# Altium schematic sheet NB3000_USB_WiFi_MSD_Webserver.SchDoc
size B; DocumentNumber: 1; SheetNumber: 1; SheetTotal: 1
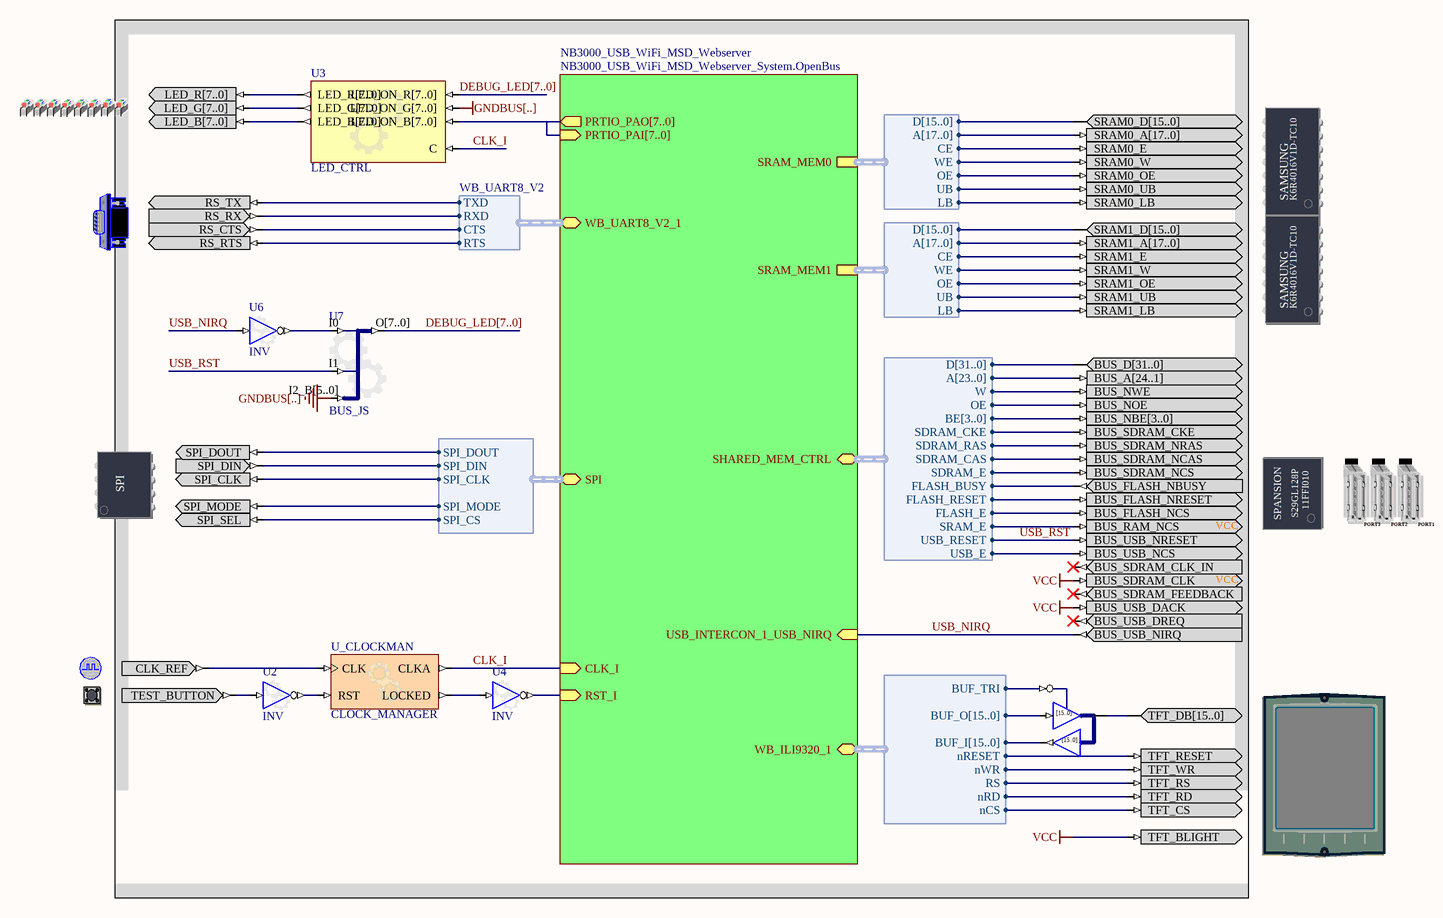
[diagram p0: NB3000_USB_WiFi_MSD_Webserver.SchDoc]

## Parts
(Parts that share a designator on the sheet are numbered #1, #2 ... from top to bottom, then left to right.)
?#1  LEDS_RGB  (value not drawn)
?#2  SRAM_DAUGHTER0  (value not drawn)
?#3  RS232CNTR  (value not drawn)
?#4  SRAM_DAUGHTER1  (value not drawn)
?#5  SHARED_FLASH_USB  (value not drawn)
?#6  SERIALFMEMORY  (value not drawn)
?#7  CLOCK_REFERENCE  (value not drawn)
?#8  TEST_BUTTON  (value not drawn)
?#9  TFT_LCD  (value not drawn)
U1  IOBUF16B  (value not drawn)
U2  INV
U3  LED_CTRL
U4  INV
U6  INV
U7  BUS_JS
U_CLOCKMAN  CLOCK_MANAGER

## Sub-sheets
NB3000_USB_WiFi_MSD_Webserver = NB3000_USB_WiFi_MSD_Webserver_System.OpenBus: SRAM_MEM0 (harness WB_MEM_CTRL_SRAM16_A18), SRAM_MEM1 (harness WB_MEM_CTRL_SRAM16_A18), RST_I (in), CLK_I (in), SHARED_MEM_CTRL (harness WB_SHARED_MEM_CTRL), USB_INTERCON_1_USB_NIRQ (in), PRTIO_PAO[7..0] (out), PRTIO_PAI[7..0] (in), WB_UART8_V2_1 (harness WB_UART8_V2), SPI (harness SPI_W_NB), WB_ILI9320_1 (harness VGA32_ILI9320)

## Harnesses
WB_MEM_CTRL_SRAM16_A18: D[15..0], A[17..0], CE, WE, OE, UB, LB
WB_SHARED_MEM_CTRL: D[31..0], A[23..0], W, OE, BE[3..0], SDRAM_CKE, SDRAM_RAS, SDRAM_CAS, SDRAM_E, FLASH_BUSY, FLASH_RESET, FLASH_E, SRAM_E, USB_RESET, USB_E
WB_UART8_V2: TXD, RXD, CTS, RTS
SPI_W_NB: SPI_DOUT, SPI_DIN, SPI_CLK, SPI_MODE, SPI_CS
VGA32_ILI9320: BUF_TRI, BUF_O[15..0], BUF_I[15..0], nRESET, nWR, RS, nRD, nCS

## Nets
GNDBUS[..]: U3.LED_ON_G[7..0] U7.I2_B[5..0]
VCC: ?#5.BUS_SDRAM_CLK ?#5.BUS_USB_DACK ?#9.TFT_BLIGHT
CLK_I: U3.C U_CLOCKMAN.CLKA ; sheet NB3000_USB_WiFi_MSD_Webserver/CLK_I
USB_NIRQ: ?#5.BUS_USB_NIRQ U6.I ; sheet NB3000_USB_WiFi_MSD_Webserver/USB_INTERCON_1_USB_NIRQ
USB_RST: ?#5.BUS_USB_NRESET U7.I1 ; sheet NB3000_USB_WiFi_MSD_Webserver/SHARED_MEM_CTRL.USB_RESET
Net?#2_SRAM0_E: ?#2.SRAM0_E ; sheet NB3000_USB_WiFi_MSD_Webserver/SRAM_MEM0.CE
Net?#2_SRAM0_LB: ?#2.SRAM0_LB ; sheet NB3000_USB_WiFi_MSD_Webserver/SRAM_MEM0.LB
Net?#2_SRAM0_OE: ?#2.SRAM0_OE ; sheet NB3000_USB_WiFi_MSD_Webserver/SRAM_MEM0.OE
Net?#2_SRAM0_UB: ?#2.SRAM0_UB ; sheet NB3000_USB_WiFi_MSD_Webserver/SRAM_MEM0.UB
Net?#2_SRAM0_W: ?#2.SRAM0_W ; sheet NB3000_USB_WiFi_MSD_Webserver/SRAM_MEM0.WE
Net?#3_RS_CTS: ?#3.RS_CTS ; sheet NB3000_USB_WiFi_MSD_Webserver/WB_UART8_V2_1.CTS
Net?#3_RS_RTS: ?#3.RS_RTS ; sheet NB3000_USB_WiFi_MSD_Webserver/WB_UART8_V2_1.RTS
Net?#3_RS_RX: ?#3.RS_RX ; sheet NB3000_USB_WiFi_MSD_Webserver/WB_UART8_V2_1.RXD
Net?#3_RS_TX: ?#3.RS_TX ; sheet NB3000_USB_WiFi_MSD_Webserver/WB_UART8_V2_1.TXD
Net?#4_SRAM1_E: ?#4.SRAM1_E ; sheet NB3000_USB_WiFi_MSD_Webserver/SRAM_MEM1.CE
Net?#4_SRAM1_LB: ?#4.SRAM1_LB ; sheet NB3000_USB_WiFi_MSD_Webserver/SRAM_MEM1.LB
Net?#4_SRAM1_OE: ?#4.SRAM1_OE ; sheet NB3000_USB_WiFi_MSD_Webserver/SRAM_MEM1.OE
Net?#4_SRAM1_UB: ?#4.SRAM1_UB ; sheet NB3000_USB_WiFi_MSD_Webserver/SRAM_MEM1.UB
Net?#4_SRAM1_W: ?#4.SRAM1_W ; sheet NB3000_USB_WiFi_MSD_Webserver/SRAM_MEM1.WE
Net?#5_BUS_FLASH_NBUSY: ?#5.BUS_FLASH_NBUSY ; sheet NB3000_USB_WiFi_MSD_Webserver/SHARED_MEM_CTRL.FLASH_BUSY
Net?#5_BUS_FLASH_NCS: ?#5.BUS_FLASH_NCS ; sheet NB3000_USB_WiFi_MSD_Webserver/SHARED_MEM_CTRL.FLASH_E
Net?#5_BUS_FLASH_NRESET: ?#5.BUS_FLASH_NRESET ; sheet NB3000_USB_WiFi_MSD_Webserver/SHARED_MEM_CTRL.FLASH_RESET
Net?#5_BUS_NOE: ?#5.BUS_NOE ; sheet NB3000_USB_WiFi_MSD_Webserver/SHARED_MEM_CTRL.OE
Net?#5_BUS_NWE: ?#5.BUS_NWE ; sheet NB3000_USB_WiFi_MSD_Webserver/SHARED_MEM_CTRL.W
Net?#5_BUS_RAM_NCS: ?#5.BUS_RAM_NCS ; sheet NB3000_USB_WiFi_MSD_Webserver/SHARED_MEM_CTRL.SRAM_E
Net?#5_BUS_SDRAM_CKE: ?#5.BUS_SDRAM_CKE ; sheet NB3000_USB_WiFi_MSD_Webserver/SHARED_MEM_CTRL.SDRAM_CKE
Net?#5_BUS_SDRAM_NCAS: ?#5.BUS_SDRAM_NCAS ; sheet NB3000_USB_WiFi_MSD_Webserver/SHARED_MEM_CTRL.SDRAM_CAS
Net?#5_BUS_SDRAM_NCS: ?#5.BUS_SDRAM_NCS ; sheet NB3000_USB_WiFi_MSD_Webserver/SHARED_MEM_CTRL.SDRAM_E
Net?#5_BUS_SDRAM_NRAS: ?#5.BUS_SDRAM_NRAS ; sheet NB3000_USB_WiFi_MSD_Webserver/SHARED_MEM_CTRL.SDRAM_RAS
Net?#5_BUS_USB_NCS: ?#5.BUS_USB_NCS ; sheet NB3000_USB_WiFi_MSD_Webserver/SHARED_MEM_CTRL.USB_E
Net?#6_SPI_CLK: ?#6.SPI_CLK ; sheet NB3000_USB_WiFi_MSD_Webserver/SPI.SPI_CLK
Net?#6_SPI_DIN: ?#6.SPI_DIN ; sheet NB3000_USB_WiFi_MSD_Webserver/SPI.SPI_DIN
Net?#6_SPI_DOUT: ?#6.SPI_DOUT ; sheet NB3000_USB_WiFi_MSD_Webserver/SPI.SPI_DOUT
Net?#6_SPI_MODE: ?#6.SPI_MODE ; sheet NB3000_USB_WiFi_MSD_Webserver/SPI.SPI_MODE
Net?#6_SPI_SEL: ?#6.SPI_SEL ; sheet NB3000_USB_WiFi_MSD_Webserver/SPI.SPI_CS
Net?#7_CLK_REF: ?#7.CLK_REF U_CLOCKMAN.CLK
Net?#8_TEST_BUTTON: ?#8.TEST_BUTTON U2.I
Net?#9_TFT_CS: ?#9.TFT_CS ; sheet NB3000_USB_WiFi_MSD_Webserver/WB_ILI9320_1.nCS
Net?#9_TFT_RD: ?#9.TFT_RD ; sheet NB3000_USB_WiFi_MSD_Webserver/WB_ILI9320_1.nRD
Net?#9_TFT_RESET: ?#9.TFT_RESET ; sheet NB3000_USB_WiFi_MSD_Webserver/WB_ILI9320_1.nRESET
Net?#9_TFT_RS: ?#9.TFT_RS ; sheet NB3000_USB_WiFi_MSD_Webserver/WB_ILI9320_1.RS
Net?#9_TFT_WR: ?#9.TFT_WR ; sheet NB3000_USB_WiFi_MSD_Webserver/WB_ILI9320_1.nWR
NetU1_T: U1.T ; sheet NB3000_USB_WiFi_MSD_Webserver/WB_ILI9320_1.BUF_TRI
NetU2_O: U2.O U_CLOCKMAN.RST
NetU4_I: U4.I U_CLOCKMAN.LOCKED
NetU4_O: U4.O ; sheet NB3000_USB_WiFi_MSD_Webserver/RST_I
NetU6_O: U6.O U7.I0

Not connected (* = marked no-connect by the designer): ?#1 LED_B[7..0] LED_G[7..0] LED_R[7..0]; ?#2 SRAM0_A[17..0] SRAM0_D[15..0]; ?#4 SRAM1_A[17..0] SRAM1_D[15..0]; ?#5 BUS_A[24..1] BUS_D[31..0] BUS_NBE[3..0] BUS_SDRAM_CLK_IN* BUS_SDRAM_FEEDBACK* BUS_USB_DREQ*; ?#9 TFT_DB[15..0]; U1 I[15..0] IO[15..0] O[15..0]; U3 LED_B[7..0] LED_G[7..0] LED_ON_B[7..0] LED_ON_R[7..0] LED_R[7..0]; U7 O[7..0]

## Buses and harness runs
bus DEBUG_LED[7..0]
bus sheet NB3000_USB_WiFi_MSD_Webserver/PRTIO_PAI[7..0] = sheet NB3000_USB_WiFi_MSD_Webserver/PRTIO_PAO[7..0]

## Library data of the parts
?#1 = LEDS_RGB: LEDS RGB; PortComponent: True
?#2 = SRAM_DAUGHTER0: Free Static RAM - Daughterboard; PortComponent: True
?#3 = RS232CNTR: DCE Serial Port Connector; PortComponent: True
?#4 = SRAM_DAUGHTER1: Free Static RAM - Daughterboard; PortComponent: True
?#5 = SHARED_FLASH_USB: Common-Bus Flash USB; PortComponent: True
?#6 = SPI_BUS: Serial SPI Flash RAM; PortComponent: True
?#7 = CLOCK_REFERENCE: Global System Clock Reference Supply; PortComponent: True
?#8 = TEST_BUTTON: Test / Reset Button; PortComponent: True
?#9 = TFT_LCD: TFT LCD Panel; PortComponent: True
U1 = IOBUF16B: 16-Bit Input/Output Buffer, Bus Version; SubClass: IOBUF; Enable: Low; Control: Common Control T; PortSize: 16; ArchiveName: GENERIC; VHDLIB_SIM: GENERIC_LIB
U2 U4 = INV: Configurable Inverter; ConfigurationParameters: {}Version[1.1]{}SignalCount[1]{}SignalWidth0[1]{}OutputOption0[Inverted]{}EnableMode[None]{}ShowPinNames[False]{}; ConfiguratorName: GENERIC_BUFFER
U3 = LED_CTRL: Configurable LED Controller; ConfigurationParameters: {}Version[1.0]{}NumLEDs[8]{}IntensityControl[Constant]{}ConstantIntensity[10]{}BusEnOut[True]{}IsRGB[True]{}
U6 = INV: Configurable Inverter; ConfiguratorName: GENERIC_BUFFER; ConfigurationParameters: {}Version[1.1]{}SignalCount[1]{}SignalWidth0[1]{}OutputOption0[Inverted]{}EnableMode[None]{}ShowPinNames[False]{}
U7 = BUS_JS: Configurable Bus Joiner/Splitter; ConfiguratorName: GENERIC_BUS_JS; ConfigurationParameters: {}Version[1.1]{}SplitterJoinerType[Joiner]{}SignalCount[3]{}SignalWidth0[1]{}GapBelow0[3000000]{}ConnectionType0[Pin]{}SignalWidth1[1]{}GapBelow1[2000000]{}ConnectionType1[Pin]{}SignalWidth2[6]{}GapBelow2[1000000]{}ConnectionType2[Pin]{}ShowPinNames[True]{}
U_CLOCKMAN = CLOCKMANAGER: Configurable Clock Manager; ConfiguratorName: GENERIC_CLOCKMANAGER; ConfigurationParameters: {}Version[1.0]{}Option_Configuration[object _1: TClockManagerPersist / VersionMajor [ 0 / VersionMinor [ 0 / InputFreq [ 20.000000000000000000 / InputName [ 'CLK' / OutputTargets [ < / item / Name [ 'CLKA' / OutFreqMin [ 40.000000000000000000 / OutFreqMax [ 40.000000000000000000 / OutPostDivider [ 1.000000000000000000 / end> / OutputDevices [ < / item / Name [ 'Spartan3AN' / Valid [ True / OutputActuals [ < / item / Name [ 'CLK0' / Multipler [ 1.000000000000000000 / Divider [ 1.000000000000000000 / OutFreq [ 20.000000000000000000 / OutputMap [ 1 / end / item / Name [ 'CLK90' / Multipler [ 1.000000000000000000 / Divider [ 1.000000000000000000 / OutPhase [ 90.000000000000000000 / OutFreq [ 20.000000000000000000 / OutputMap [ 2 / end / item / Name [ 'CLK180' / Multipler [ 1.000000000000000000 / Divider [ 1.000000000000000000 / OutPhase [ 180.000000000000000000 / OutFreq [ 20.000000000000000000 / OutputMap [ 3 / end / item / Name [ 'CLK270' / Multipler [ 1.000000000000000000 / Divider [ 1.000000000000000000 / OutPhase [ 270.000000000000000000 / OutFreq [ 20.000000000000000000 / OutputMap [ 4 / end / item / Name [ 'CLK2X' / Multipler [ 2.000000000000000000 / Divider [ 1.000000000000000000 / OutFreq [ 40.000000000000000000 / OutputMap [ 0 / end / item / Name [ 'CLKDV' / Multipler [ 1.000000000000000000 / Divider [ 2.000000000000000000 / OutFreq [ 10.000000000000000000 / OutputMap [ 5 / end / item / Name [ 'CLK2X180' / Multipler [ 1.000000000000000000 / Divider [ 1.000000000000000000 / OutPhase [ 180.000000000000000000 / OutFreq [ 40.000000000000000000 / OutputMap [ 6 / end / item / Name [ 'CLKFX' / Multipler [ 2.000000000000000000 / Divider [ 1.000000000000000000 / OutFreq [ 40.000000000000000000 / OutputMap [ 7 / end / item / Name [ 'CLKFX180' / Multipler [ 1.000000000000000000 / Divider [ 1.000000000000000000 / OutPhase [ 180.000000000000000000 / OutFreq [ 40.000000000000000000 / OutputMap [ 8 / end> / InternalActuals [ <> / CustomVars [ <> / end / item / Name [ 'Cyclone3' / Valid [ True / OutputActuals [ < / item / Name [ 'C0' / Multipler [ 2.000000000000000000 / Divider [ 1.000000000000000000 / OutFreq [ 40.000000000000000000 / OutputMap [ 0 / end / item / Name [ 'C1' / Multipler [ 1.000000000000000000 / Divider [ 1.000000000000000000 / OutFreq [ 20.000000000000000000 / OutputMap [ 1 / end / item / Name [ 'C2' / Multipler [ 1.000000000000000000 / Divider [ 1.000000000000000000 / OutFreq [ 20.000000000000000000 / OutputMap [ 2 / end / item / Name [ 'C3' / Multipler [ 1.000000000000000000 / Divider [ 1.000000000000000000 / OutFreq [ 20.000000000000000000 / OutputMap [ 3 / end / item / Name [ 'C4' / Multipler [ 1.000000000000000000 / Divider [ 1.000000000000000000 / OutFreq [ 20.000000000000000000 / OutputMap [ 4 / end> / InternalActuals [ <> / CustomVars [ <> / end> / MinInputFreq [ 1.000000000000000000 / MaxInputFreq [ 280.000000000000000000 / MinOutputFreq [ 18.000000000000000000 / MaxOutputFreq [ 210.000000000000000000 / MaxOutputCount [ 9 / end]{}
